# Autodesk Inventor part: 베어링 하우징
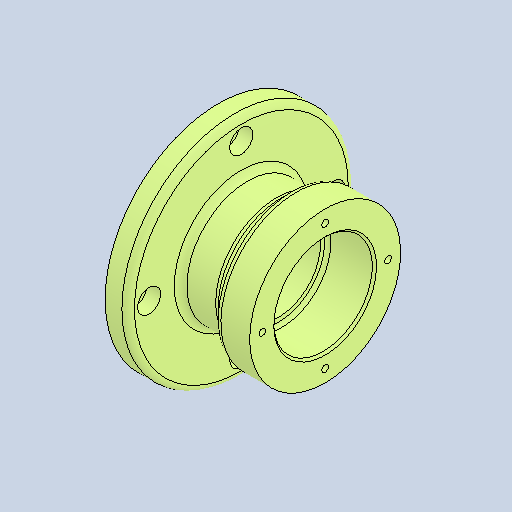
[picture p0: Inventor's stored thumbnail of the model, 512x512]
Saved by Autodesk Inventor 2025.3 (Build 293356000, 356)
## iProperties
Created: 2026-01
Part Number: 베어링 하우징
Material: 알루미늄 6061
Document SubType Name: Modeling
Designer: pc6
Density: 2.7 g/cm^3
Appearance: 기본값
Author: jhkim
Sending System: Autodesk Inventor 2026
Preprocessor: ST-DEVELOPER v20.1
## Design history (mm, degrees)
feature "솔리드1"
node "솔리드2"
